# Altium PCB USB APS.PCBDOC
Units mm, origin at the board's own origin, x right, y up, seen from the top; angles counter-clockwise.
Board outline 92.58 x 101.6 mm, 2 copper layers (Top Layer, Bottom Layer); 29 components, 24 nets, 157 pads, 0 vias.
Unrouted connection lines stored in the file: 13.
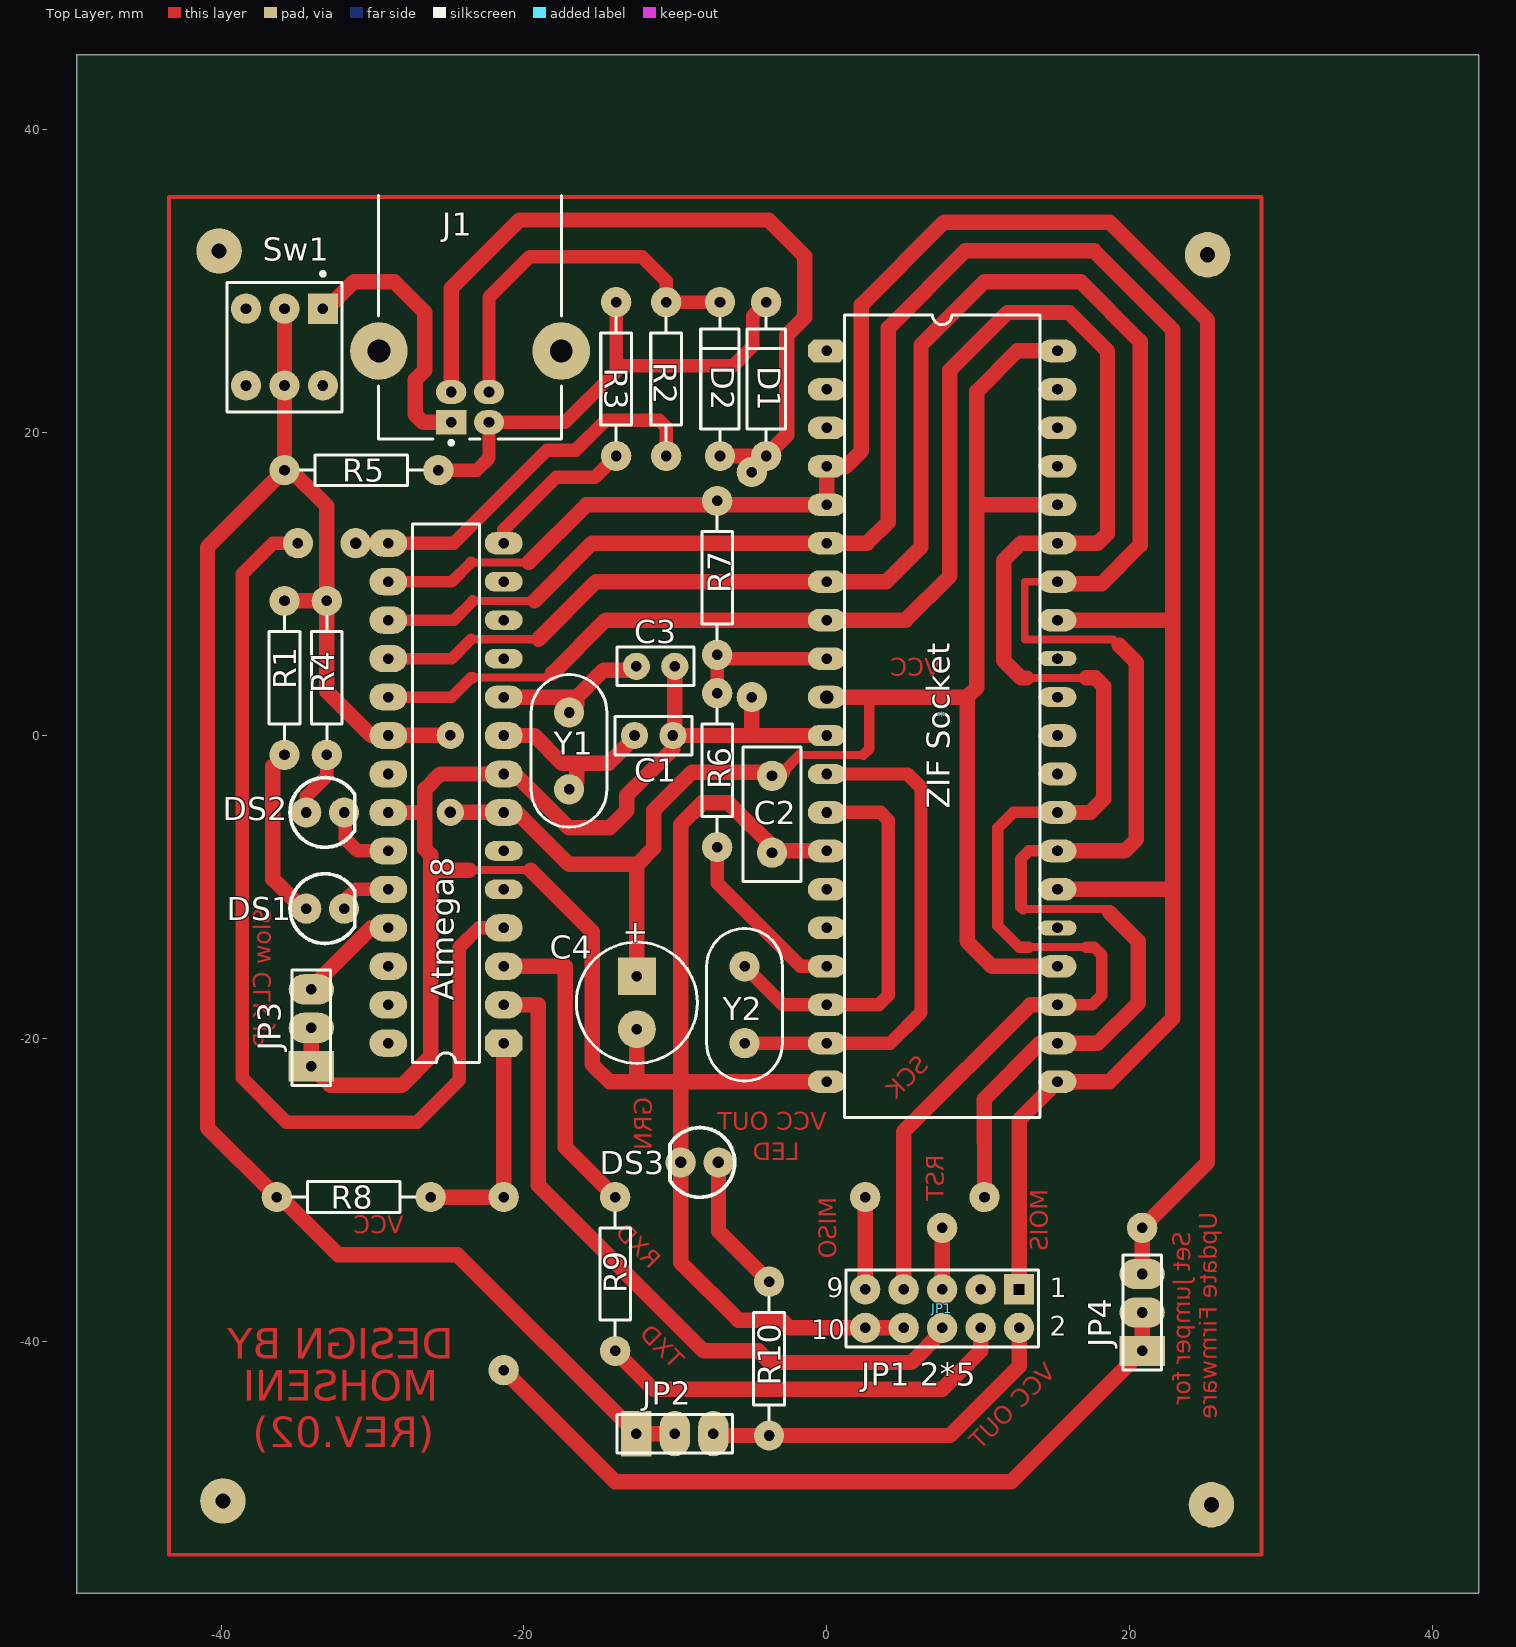
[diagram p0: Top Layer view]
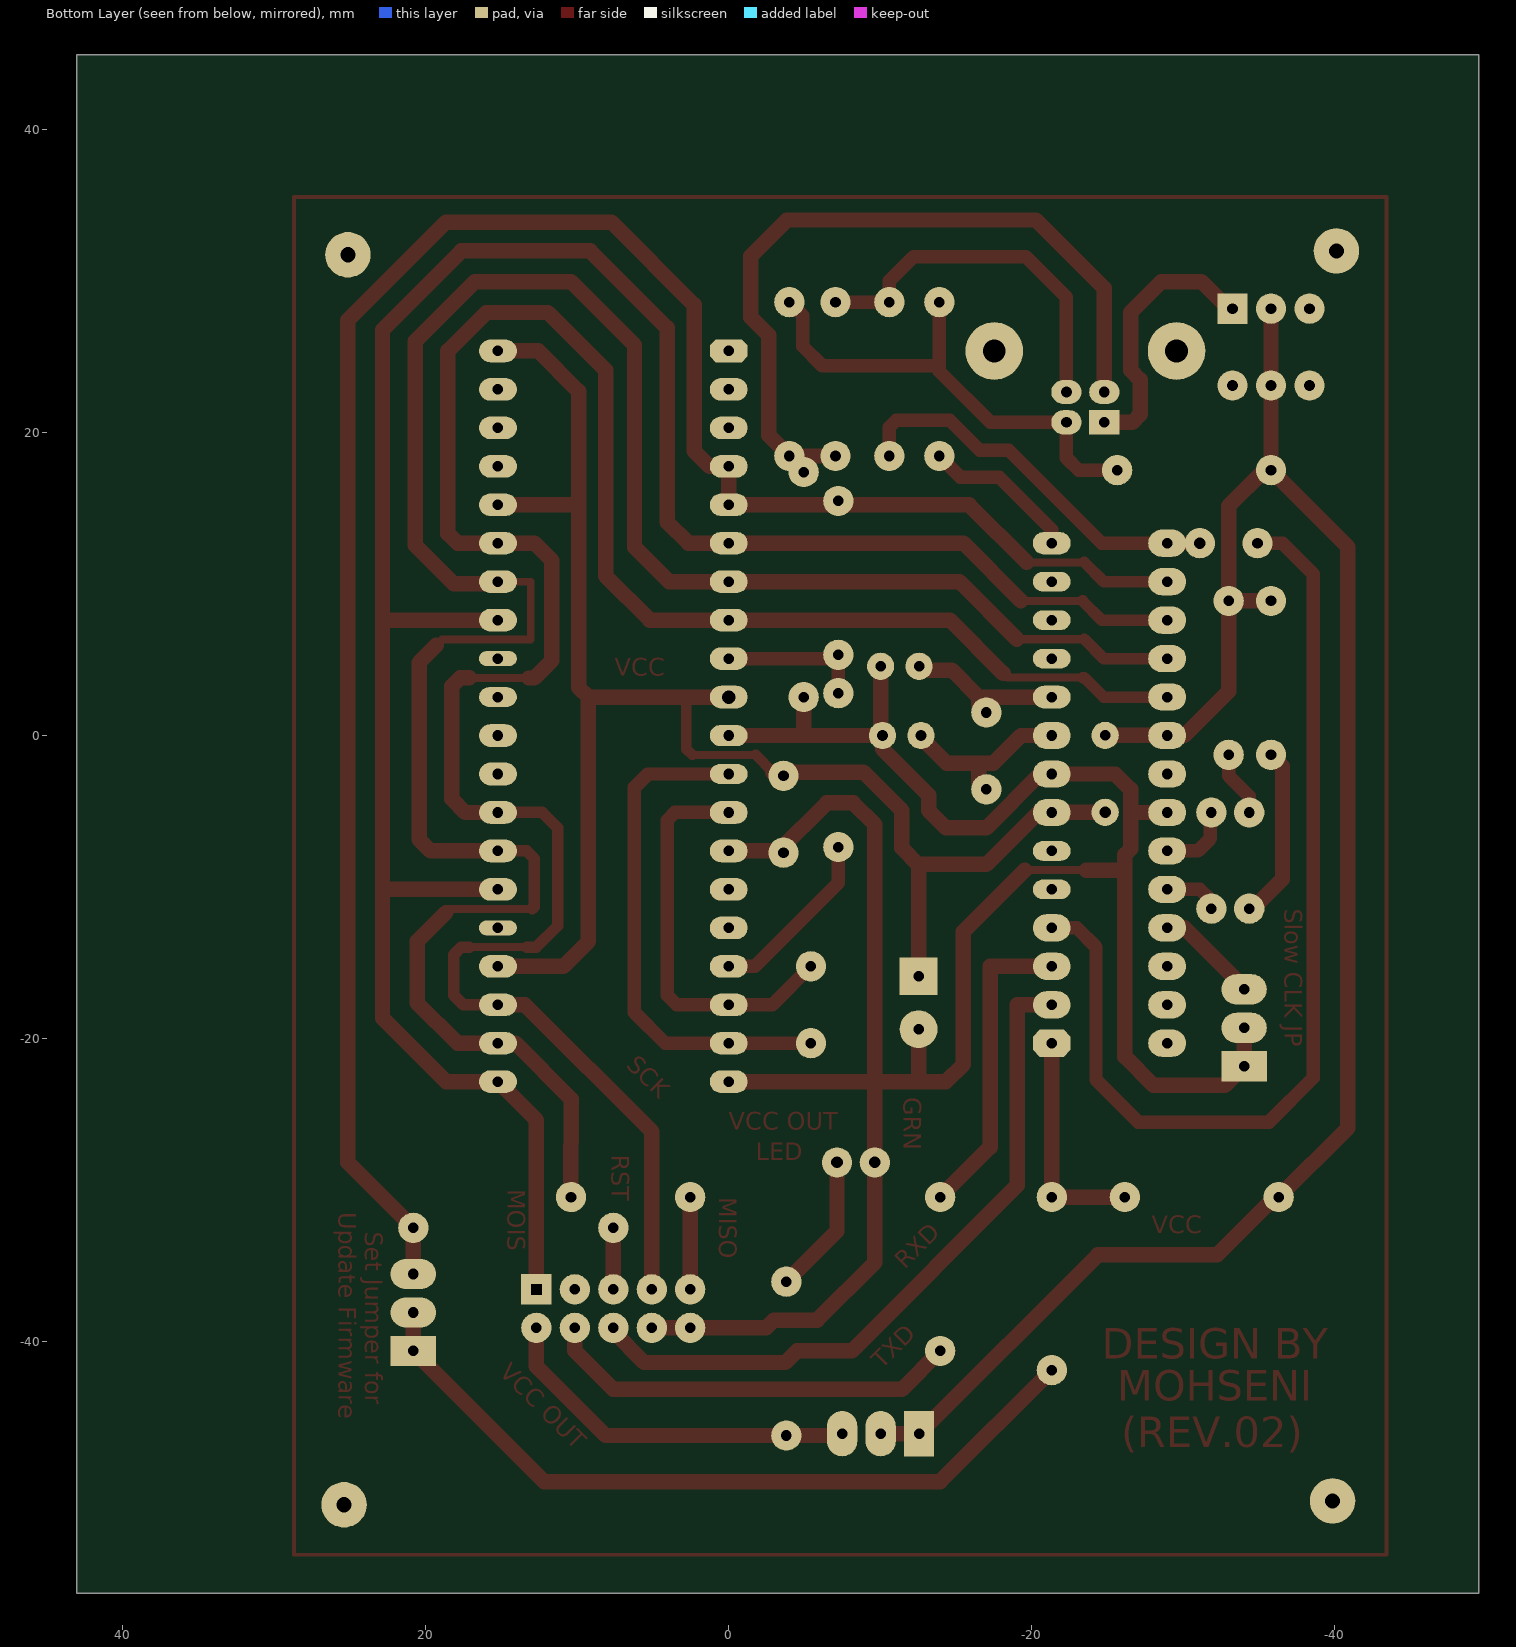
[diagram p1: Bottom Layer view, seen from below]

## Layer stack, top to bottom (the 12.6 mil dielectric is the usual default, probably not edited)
Top Solder: solder mask 0.0102, Solder Resist, Dk 3.5
Top Layer: signal copper 0.0356
Dielectric1: dielectric 0.32, FR-4, Dk 4.8
Bottom Layer: signal copper 0.0356
Bottom Solder: solder mask 0.0102, Solder Resist, Dk 3.5

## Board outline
-49.53,-56.642 43.053,-56.642 43.053,44.958 -49.53,44.958

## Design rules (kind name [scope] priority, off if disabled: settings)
Clearance [All] p1: gap=0.254
FabricationTestPointUsage TestPointUsage [All] p1: valid=0 allowmultiple=FALSE
FabricationTestpoint Testpoint [All] p1: side=3 testpointundercomponent=TRUE minsize=1.016 maxsize=2.54 preferedsize=1.524 minholesize=0 maxholesize=1.016 preferedholesize=0.813 testpointgrid=0.025 allowsidetop=TRUE allowsidebottom=TRUE usegrid=TRUE gridtolerance=0
PolygonConnect [All] p1: connectstyle=Relief reliefconductorwidth=0.254 reliefentries=4 polygonreliefangle="90 Angle" airgapwidth=0.254
RoutingVias [All] p1: holewidth=0.711 width=1.27 viastyle="Through Hole" minholewidth=0.711 minwidth=1.27 maxholewidth=0.711 maxwidth=1.27
SolderMaskExpansion [All] p1: expansion=0.102
UnpouredPolygon [All] p1: allowunpoured=FALSE
Width [All] p1: maxlimit=8 minlimit=0.254 preferedwidth=1.016 bottomlayer_prefwidth=0.254 minimp=50.000000 maximp=50.000000 favimp=50.000000
27 further rules are at their usual default settings.

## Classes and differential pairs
component class "USB APS": * Atmega8 C1 C2 C3 C4 D1 D2 DS1 DS2 J1 JP1 JP3 R1 R2 R3 R4 R5 R6 R7 Sw1 Y1 Y2

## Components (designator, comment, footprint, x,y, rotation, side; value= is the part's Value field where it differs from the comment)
* "zif sucket" 40P6 7.62,1.27 r270 top
Atmega8 "ATmega8-16PC" 28P3 -25.146,-3.81 r90 top (schematic designator U1)
C1 "Cap" RAD-0.1 -11.43,0 r0 top
C2 "Cap" RAD-0.2 -3.617,-5.198 r90 top
C3 "Cap" RAD-0.1 -11.303,4.572 r0 top
C4 "Cap Pol1" CAPPR3.5-8x5 -12.541,-17.644 r270 top
D1 "D Zener" DIODE-0.4 -4.004,23.543 r90 top
D2 "D Zener" DIODE-0.4 -7.052,23.543 r90 top
DS1 "LED0" LED3mm#1 -31.877,-11.43 r180 top
DS2 "LED0" LED3mm#1 -31.877,-5.08 r180 top
DS3 "LED0" LED3mm#2 -9.652,-28.194 r0 top (schematic designator DS1)
J1 "1-1470156-1" 1-1470156 -23.556,35.696 r90 top
JP1 "Header 5X2" HDR2X5 2.54,-39.116 r0 top
JP2 "Header 3" HDR1X3 -12.573,-46.101 r0 top (schematic designator JP3)
JP3 "Header 3" HDR1X3 -34.036,-21.844 r90 top
JP4 "Header 3" HDR1X3 20.828,-40.64 r90 top (schematic designator JP3)
R1 "Res1" AXIAL-0.4 -35.814,3.81 r270 top
R2 "Res1" AXIAL-0.4 -10.608,23.543 r270 top
R3 "Res1" AXIAL-0.4 -13.91,23.543 r270 top
R4 "Res1" AXIAL-0.4 -33.02,3.81 r270 top
R5 "Res1" AXIAL-0.4 -30.734,17.526 r180 top
R6 "Res1" AXIAL-0.4 -7.239,-2.286 r90 top
R7 "Res1" AXIAL-0.4 -7.239,10.414 r90 top
R8 "Res1" AXIAL-0.4 -31.242,-30.48 r180 top (schematic designator R1)
R9 "Res1" AXIAL-0.4 -13.97,-35.56 r270 top (schematic designator R1)
R10 "Res1" AXIAL-0.4 -3.81,-41.148 r270 top (schematic designator R1)
Sw1 "SW-DPDT" DPDT-6 -35.814,25.654 r270 top (schematic designator S1)
Y1 "XTAL" "xtal - duplicate" -17.018,1.524 r270 top
Y2 "XTAL" "xtal - duplicate" -5.429,-20.32 r90 top

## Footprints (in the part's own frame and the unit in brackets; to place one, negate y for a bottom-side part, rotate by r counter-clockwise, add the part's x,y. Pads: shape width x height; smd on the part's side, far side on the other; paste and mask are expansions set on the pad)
1-1470156 [mm] "Connector; USB1.1, Type B, Thru-Hole; 4 Position; Right Angle"
  rect 1.6x2 hole 0.7: 1(-15.01,1.25)
  oval 1.6x2 hole 0.7: 2(-15.01,-1.25) 3(-13.01,-1.25) 4(-13.01,1.25)
  round 3.8 hole 1.5: 5(-10.3,6.02) 6(-10.3,-6.02)
  silkscreen extent -16.48,-6.05 -0.02,6.05
28P3 [mm] "DIP; 28 Leads; Row Spacing 7.62 mm; Pitch 2.54 mm"
  oct 1.8x2.5 hole 0.7: 1(-16.51,-3.81)
  oval 1.8x2.5 hole 0.7: 2(-13.97,-3.81) 3(-11.43,-3.81) 4(-8.89,-3.81) 7(-1.27,-3.81) 8(1.27,-3.81) 9(3.81,-3.81) 15(16.51,3.81) 16(13.97,3.81) 17(11.43,3.81) 18(8.89,3.81) 19(6.35,3.81) 20(3.81,3.81) 21(1.27,3.81) 22(-1.27,3.81) 23(-3.81,3.81) 24(-6.35,3.81) 25(-8.89,3.81) 26(-11.43,3.81) 27(-13.97,3.81) 28(-16.51,3.81)
  oval 1.3x2.5 hole 0.7: 5(-6.35,-3.81) 6(-3.81,-3.81) 11(8.89,-3.81) 12(11.43,-3.81) 13(13.97,-3.81)
  oval 1.5x2.5 hole 0.7: 10(6.35,-3.81) 14(16.51,-3.81)
  silkscreen extent -17.78,-2.23 17.78,2.23
40P6 [mm] "DIP; 40 Leads; Row Spacing 15.24 mm; Pitch 2.54 mm"
  oct 1.5x2.5 hole 0.7: 1(-24.13,-7.62)
  oval 1.5x2.5 hole 0.7: 2(-21.59,-7.62) 3(-19.05,-7.62) 4(-16.51,-7.62) 5(-13.97,-7.62) 6(-11.43,-7.62) 7(-8.89,-7.62) 8(-6.35,-7.62) 9(-3.81,-7.62) 13(6.35,-7.62) 14(8.89,-7.62) 15(11.43,-7.62) 16(13.97,-7.62) 17(16.51,-7.62) 18(19.05,-7.62) 19(21.59,-7.62) 20(24.13,-7.62) 21(24.13,7.62) 22(21.59,7.62) 23(19.05,7.62) 24(16.51,7.62) 26(11.43,7.62) 27(8.89,7.62) 28(6.35,7.62) 29(3.81,7.62) 30(1.27,7.62) 33(-6.35,7.62) 34(-8.89,7.62) 35(-11.43,7.62) 36(-13.97,7.62) 37(-16.51,7.62) 38(-19.05,7.62) 39(-21.59,7.62) 40(-24.13,7.62)
  oval 1.5x2.5 hole 0.9: 10(-1.27,-7.62)
  oval 1.4x2.5 hole 0.7: 11(1.27,-7.62)
  oval 1.3x2.5 hole 0.7: 12(3.81,-7.62) 31(-1.27,7.62)
  oval 1x2.5 hole 0.7: 25(13.97,7.62) 32(-3.81,7.62)
  silkscreen extent -26.5,-6.45 26.5,6.45
AXIAL-0.4 [mm] "Resistor; 2 Leads"
  round 2 hole 0.7: 1(-5.08,0) 2(5.08,0)
  silkscreen extent -4.06,-1.02 4.06,1.02
CAPPR3.5-8x5 [mm]
  rect 2.5x2.5 hole 0.7: 1(-1.75,0)
  round 2.5 hole 0.7: 2(1.75,0)
  silkscreen extent -4,-4 4,4
DIODE-0.4 [mm]
  round 2 hole 0.7: 1(-5.08,0) 2(5.08,0)
  silkscreen extent -4.06,-1.27 4.06,1.27
DPDT-6 [mm] "Double-Pole, Double-Throw Switch; 6 Leads"
  rect 2x2 hole 0.7: 1(-2.54,2.54)
  round 2 hole 0.7: 2(-2.54,0) 3(-2.54,-2.54) 4(2.54,-2.54) 5(2.54,0) 6(2.54,2.54)
  silkscreen extent -4.96,-3.81 4.28,3.81
HDR1X3 [mm] "Connector; Header; 3 Position"
  rect 2x3 hole 0.7: 1(0,0)
  oval 2x3 hole 0.7: 2(2.54,0) 3(5.08,0)
  silkscreen extent -1.27,-1.27 6.35,1.27
HDR2X5 [mm] "Connector; Header; 5x2 Position"
  round 2 hole 0.7: 1(0,0) 2(0,2.54) 3(2.54,0) 4(2.54,2.54) 5(5.08,0) 6(5.08,2.54) 7(7.62,0) 8(7.62,2.54) 9(10.16,0)
  rect 2x2 hole 0.7 square: 10(10.16,2.54)
  silkscreen extent -1.27,-1.27 11.43,3.81
LED3mm#1 [mm]
  round 2 hole 0.7: 1(2.5,0) 2(0,0)
  silkscreen extent -0.7,-2.3 3.57,2.3
LED3mm#2 [mm]
  round 2 hole 0.762: 1(2.5,0) 2(0,0)
  silkscreen extent -0.7,-2.3 3.57,2.3
RAD-0.1 [mm]
  round 1.8 hole 0.7: 1(-1.27,0) 2(1.27,0)
  silkscreen extent -2.54,-1.27 2.54,1.27
RAD-0.2 [mm]
  round 2 hole 0.7: 1(-2.54,0) 2(2.54,0)
  silkscreen extent -4.44,-1.91 4.44,1.91
"xtal - duplicate" [mm]
  round 2 hole 0.7: 1(0,0) 2(5.08,0)
  silkscreen extent -2.5,-2.5 7.58,2.5

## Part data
*: library part Component_1
Atmega8: "8-Bit AVR Microcontroller with 8K Bytes of In-System Programmable Flash Memory"
C1 C2 C3: "Capacitor"
C4: "Polarized Capacitor (Radial)"
D1 D2: "Zener Diode"
DS1 DS2 DS3: "Typical INFRARED GaAs LED"
J1: "USB 1.1, Right Angle, Thru-Hole, B Type, Receptacle, 4 Position, White"
JP1: "Header, 5-Pin, Dual row"
JP2 JP3 JP4: "Header, 3-Pin"
R1 R2 R3 R4 R5 R6 R7 R8 R9 R10: "Resistor"
Sw1: "Double-Pole, Double-Throw Switch"
Y1 Y2: "Crystal Oscillator"

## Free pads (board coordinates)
  round 3 hole 1: 0(-40.132,32.004) 0(-39.878,-50.546) 0(25.146,31.75) 0(25.4,-50.8)
  round 2 hole 0.7: 0(-34.925,12.7) 2(-21.336,-30.48) 3(-21.336,-41.91) 4(10.414,-30.48) 5(2.54,-30.48) 7(-4.953,17.399) 8(-4.953,2.54)
  round 1.8 hole 0.762: 0(-24.86,-5.071)
  round 1.8 hole 0.7: 1(-24.86,0.009)
  round 2 hole 0.762: 2(-31.115,12.7)
  round 2 hole 0.7 paste+1 mask+0.102: 3(7.62,-32.512) 3(20.828,-32.512)

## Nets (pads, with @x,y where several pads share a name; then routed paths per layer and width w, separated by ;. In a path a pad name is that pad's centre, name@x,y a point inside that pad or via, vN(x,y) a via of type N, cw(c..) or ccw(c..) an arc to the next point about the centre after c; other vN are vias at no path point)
CLK: JP1.8
GND: *.11 *.14 *.20 Atmega8.8 Atmega8.22 C1.2 C2.1 C3.2 C4.2 D1.1 D2.1 DS3.2 J1.4 JP1.1 JP1.3 JP3.1 JP3.2 pad.7 pad.8 | length 218.6
  Top Layer w0.53: -23.622,-8.89 -19.558,-8.89
  Top Layer w1.016: JP3.2 JP3.1 -32.775,-23.105 -28.058,-23.105 -26.162,-21.209 -26.162,-8.89 ; Atmega8.22 -26.67,-5.08 -26.543,-5.207 ; J1.4 -24.806,29.527 -20.288,34.045 -3.838,34.045 -1.464,31.671 -1.464,27.607 -2.648,26.423 -2.648,19.819 D1.1 D2.1 ; -23.622,-8.89 -26.162,-8.89 ; Atmega8.8@-21.59,-2.794 -21.844,-2.54 -25.527,-2.54 -26.543,-3.556 -26.543,-5.207 ; Atmega8.8 -20.574,-2.54 -17.018,-6.096 -14.351,-6.096 -13.208,-4.953 -13.208,-3.937 -10.16,-0.889 -10.16,-0.127 C1.2@-10.033,0 ; -19.558,-8.89 -15.494,-12.954 -15.494,-21.717 -14.351,-22.86 -9.652,-22.86 ; -12.541,-22.828 C4.2 ; C3.2@-10.033,4.318 C1.2@-10.033,0 ; pad.8 -4.953,0 ; *.20 -9.652,-22.86 ; *.14 -3.302,-7.62 -6.477,-4.445 -8.223,-4.445 -9.652,-5.874 -9.652,-22.86 ; *.11 -4.953,0 ; JP1.3 JP1.1 -2.476,-39.116 -2.984,-38.608 -5.842,-38.608 -9.652,-34.798 -9.652,-22.86 ; -26.543,-5.207 -26.543,-7.493 -26.162,-7.874 -26.162,-8.89 ; C1.2@-10.033,0 -4.953,0
MISO: *.7 *.22 *.27 *.34 Atmega8.18 JP1.2 pad.4 pad.5 | length 164.9
  Top Layer w0.254: *.27 *.27@16.129,-7.62 ; *.34 *.34@15.367,10.16
  Top Layer w0.381: 18.427,-11.442 18.669,-11.684
  Top Layer w0.508: 13.093,6.338 13.081,6.35 13.081,10.16 *.34 ; 18.935,6.338 19.304,5.969
  Top Layer w0.53: -23.495,6.359 -19.041,6.359 ; 12.966,-11.442 18.427,-11.442 ; 13.093,6.338 18.935,6.338
  Top Layer w0.762: Atmega8.18 -24.774,5.08 -23.495,6.359 ; 12.966,-11.442 12.827,-11.303 12.827,-8.128 13.335,-7.62 *.27
  Top Layer w1.016: -19.041,6.359 -15.24,10.16 *.7 3.937,10.16 6.223,12.446 6.223,25.781 10.414,29.972 16.764,29.972 20.701,26.035 20.701,12.573 18.161,10.033 *.34@15.367,10.033 ; JP1.2 pad.5 ; pad.4@10.42,-29.972 10.401,-24.003 14.084,-20.32 *.22 17.907,-20.32 20.574,-17.653 20.574,-13.589 18.669,-11.684 ; *.27 19.685,-7.62 20.447,-6.858 20.447,4.826 19.304,5.969
MOIS: *.6 *.21 *.26 *.33 Atmega8.17 JP1.10 | length 159.7
  Top Layer w0.254: *.26 18.415,-10.16
  Top Layer w0.508: Atmega8.17@-29.083,7.62 Atmega8.17
  Top Layer w0.53: -23.368,8.89 -19.304,8.89
  Top Layer w0.762: Atmega8.17 -24.638,7.62 -23.368,8.89
  Top Layer w1.016: -19.304,8.89 -15.494,12.7 *.6 2.667,12.7 4.064,14.097 4.064,26.924 9.144,32.004 17.653,32.004 22.86,26.797 22.86,7.62 ; JP1.10 12.7,-25.4 *.21 18.669,-22.86 22.86,-18.669 22.86,-10.16 ; *.26 22.86,-10.16 ; *.33 22.86,7.62 ; 22.86,-10.16 22.86,7.62
NetD1_2: D1.2 J1.2 R3.1 R5.1 | length 32.7
  Top Layer w0.889: R5.1@-25.146,17.526 -23.114,17.526 -22.306,18.334 J1.2 -17.287,20.686 -13.91,24.063 -13.91,24.432 ; R3.1 -13.91,24.432 ; D1.2 -4.893,27.734 -4.893,25.702 -6.163,24.432 -13.91,24.432
NetD2_2: D2.2 J1.3 R2.1 | length 24.7
  Top Layer w0.889: J1.3 -22.306,28.951 -19.625,31.632 -12.22,31.632 -10.608,30.02 R2.1 D2.2
NetDS1_1: DS1.1 R1.2 | length 11.5
  Top Layer w1.016: R1.2 -36.576,-2.032 -36.576,-9.485 DS1.1@-34.504,-11.557
NetDS1_2: Atmega8.24 DS1.2 | length 3.7
  Top Layer w0.889: DS1.2@-31.75,-11.43 -31.75,-10.795 -31.115,-10.16 Atmega8.24
NetDS2_1: DS2.1 R4.2 | length 4.9
  Top Layer w0.889: DS2.1@-34.377,-5.588 -34.377,-4.024 -33.02,-2.667 R4.2
NetDS2_2: Atmega8.23 DS2.2 | length 5
  Top Layer w0.889: DS2.2@-31.813,-5.016 -31.813,-6.794 -30.988,-7.62 Atmega8.23
NetJ1_1: J1.1 Sw1.1 Sw1.4 | length 17.4
  Top Layer w1.016: Sw1.1@-32.861,28.33 -31.219,29.972 -28.575,29.972 -26.543,27.94 -26.543,24.13 -27.178,23.495 -27.178,21.209 -26.655,20.686 J1.1
NetJP3_3: Atmega8.25 JP3.3 | length 6.8
  Top Layer w1.016: JP3.3@-34.099,-16.7 -30.099,-12.7 Atmega8.25
NetR2_2: Atmega8.4 Atmega8.15 pad.0@-34.925,12.7 pad.2@-31.115,12.7 R2.2 | length 93.1
  Top Layer w0.889: pad.0@-34.544,12.7 -36.576,12.7 -38.608,10.668 -38.608,-22.606 -35.687,-25.527 -27.051,-25.527 -24.257,-22.733 -24.257,-13.97 -22.987,-12.7 Atmega8.4 ; pad.2@-31.115,12.7 Atmega8.15 -24.638,12.7 -18.494,18.844 -16.589,18.844 -14.605,20.828 -11.068,20.828 -10.608,20.368 R2.2
NetR3_2: Atmega8.14 R3.2 | length 10.3
  Top Layer w0.889: Atmega8.14 -21.336,13.589 -17.859,17.066 -15.307,17.066 R3.2
Reset: 
RST: *.4 *.5 *.9 *.17 Atmega8.1 Atmega8.16 JP1.6 JP4.1 JP4.2 JP4.3 pad.2@-21.336,-30.48 pad.3 R6.1 R6.2 R7.1 R7.2 R8.1 | length 230.2
  Top Layer w0.53: -23.495,11.43 -19.685,11.43
  Top Layer w0.762: Atmega8.16 -24.765,10.16 -23.495,11.43
  Top Layer w0.889: R6.1@-7.493,-7.62 R6.1 -7.239,-9.738 -1.737,-15.24 *.17 ; R6.2 -7.239,5.08 *.9
  Top Layer w1.016: R8.1 pad.2@-21.336,-30.48 ; pad.3@-21.336,-41.91 -13.97,-49.276 12.192,-49.276 JP4.1 JP4.2 ; pad.2@-21.336,-29.972 Atmega8.1 ; -19.685,11.43 -15.875,15.24 *.5 *.4 1.27,17.78 2.286,18.796 2.286,28.448 7.747,33.909 18.669,33.909 25.146,27.432 25.146,-28.194 20.828,-32.512 JP4.3 ; JP1.6 pad.3@7.62,-32.512
RXD: Atmega8.2 JP1.5 | length 46.8
  Top Layer w1.016: Atmega8.2 -19.05,-17.78 -19.05,-29.718 -8.128,-40.64 -4.508,-40.64 -3.746,-41.402 5.588,-41.402 7.62,-39.37 JP1.5
SCK: *.8 *.23 *.28 *.35 Atmega8.19 JP1.4 | length 159.9
  Top Layer w0.508: -18.406,3.819 -18.12,4.105
  Top Layer w0.53: -23.368,3.819 -18.406,3.819 ; 13.208,3.798 17.145,3.81 ; 13.335,-13.97 17.145,-13.97
  Top Layer w0.762: Atmega8.19 -24.774,2.54 -23.495,3.819 -23.368,3.819 ; 13.335,-13.97 12.7,-13.97 11.303,-12.573 11.303,-6.096 12.319,-5.08 *.28 ; *.23 17.526,-17.78 18.161,-17.145 18.161,-14.478 17.653,-13.97 17.145,-13.97
  Top Layer w1.016: -18.12,4.105 -14.605,7.62 *.8 5.207,7.62 8.128,10.541 8.128,24.13 11.938,27.94 16.002,27.94 18.542,25.4 18.542,13.335 17.907,12.7 *.35 12.827,12.7 11.684,11.557 11.684,4.953 12.839,3.798 13.208,3.798 ; JP1.4@5.074,-36.576 5.074,-26.156 13.449,-17.78 *.23 ; *.28 17.399,-5.08 18.288,-4.191 18.288,3.267 17.745,3.81 17.145,3.81
TXD: Atmega8.3 JP1.7 R9.1 R9.2 | length 48.4
  Top Layer w1.016: Atmega8.3 -17.272,-15.24 -17.272,-27.178 R9.1 ; R9.2 -11.43,-43.18 7.62,-43.18 10.16,-40.64 JP1.7
VCC: *.10 *.24 *.36 *.40 Atmega8.7 Atmega8.20 C2.2 C4.1 DS3.1 JP1.9 JP2.1 JP2.2 JP2.3 pad.0@-24.86,-5.071 pad.1 R1.1 R4.1 R5.2 R8.2 R10.1 R10.2 Sw1.2 Sw1.5 | length 265.1
  Top Layer w0.53: -1.778,-1.27 2.413,-1.27
  Top Layer w0.7: C2.2@-2.921,-2.413 -1.778,-1.27 ; 2.413,-1.27 2.794,-0.889 2.794,2.54
  Top Layer w1.016: R1.1 R4.1 ; R5.2@-35.814,18.034 Sw1.5 Sw1.2 ; R4.1@-32.893,8.89 R4.1 ; pad.0@-24.86,-5.071 -21.345,-5.071 Atmega8.7 -20.447,-5.08 -17.018,-8.509 -12.509,-8.509 ; pad.1 -28.947,0.009 Atmega8.20 -30.099,0 -33.02,2.921 R4.1 ; C4.1 -12.541,-8.541 -12.509,-8.509 ; JP2.2 JP2.1 -24.384,-34.29 -32.258,-34.29 -36.068,-30.48 R8.2 -40.894,-25.908 -40.894,12.446 R5.2 -35.401,17.526 -33.02,15.145 R4.1 ; JP2.3@-7.493,-46.228 R10.2@-3.302,-46.228 ; DS3.1@-7.152,-28.702 -7.152,-32.726 R10.1 ; R10.2@-3.048,-46.228 8.128,-46.228 12.7,-41.656 JP1.9 ; C2.2@-2.921,-2.413 -8.89,-2.413 -11.43,-4.953 -11.43,-7.43 -12.509,-8.509 ; *.10 2.794,2.54 9.271,2.54 ; *.24 10.922,-15.24 9.271,-13.589 9.271,2.54 ; *.36 9.906,15.24 ; *.40 12.573,25.4 9.906,22.733 9.906,15.24 ; 9.271,2.54 9.906,3.175 9.906,15.24
X1: Atmega8.9 C1.1 Y1.2 | length 12.2
  Top Layer w1.016: Atmega8.9 -19.304,0 -17.47,-1.834 -16.51,-1.834 ; Y1.2 -16.51,-3.048 -16.51,-1.834 ; C1.1@-12.573,0 -14.407,-1.834 -16.51,-1.834
X2: Atmega8.10 C3.1 Y1.1 | length 10.1
  Top Layer w1.016: Atmega8.10 -16.51,2.54 ; Y1.1 -16.51,2.032 -16.51,2.54 ; C3.1@-13.208,4.318 -14.732,4.318 -16.51,2.54
X21: *.12 *.19 Y2.1 | length 33.9
  Top Layer w0.889: Y2.1 *.19 4.191,-20.32 6.223,-18.288 6.223,-3.429 5.334,-2.54 *.12
X22: *.13 *.18 Y2.2 | length 26.6
  Top Layer w0.889: Y2.2 -2.889,-17.78 *.18 3.429,-17.78 4.064,-17.145 4.064,-5.588 3.556,-5.08 *.13
pads on no net: *.1 *.2 *.3 *.15 *.16 *.25 *.29 *.30 *.31 *.32 *.37 *.38 *.39 Atmega8.5 Atmega8.6 Atmega8.11 Atmega8.12 Atmega8.13 Atmega8.21 Atmega8.26 Atmega8.27 Atmega8.28 J1.5 J1.6 Sw1.3 Sw1.6
copper on no net: | length 323.6
  Top Layer w0.254: -43.434,-54.102 -43.434,35.56 28.702,35.56 28.702,-54.102 -43.434,-54.102

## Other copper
Top Layer:
  text "VCC" at 7.52,3.556 h2
  text "Slow CLK JP" at -36.322,-11.43 h2 r90
  text "SCK" at 7.112,-22.098 h2 r45
  text "GRN" at -11.176,-23.876 h2 r90
  text "VCC OUT" at 0,-26.416 h2
  text "RST" at 8.128,-27.686 h2 r90
  text "LED" at -1.778,-28.448 h2
  text "MOIS" at 14.986,-29.972 h2 r90
  text "MISO" at 1.016,-30.48 h2 r90
  text "Update Firmware" at 26.162,-31.496 h2 r90
  text "Set Jumper for" at 24.384,-32.766 h2 r90
  text "VCC" at -27.94,-33.274 h2
  text "RXD" at -11.938,-35.56 h2 r315
  text "DESIGN BY" at -24.638,-41.148 h2
  text "TXD" at -10.414,-42.164 h2 r315
  text "VCC OUT" at 15.494,-42.418 h2 r45
  text "MOHSENI" at -25.654,-43.942 h2
  text "(REV.02)" at -25.908,-46.99 h2

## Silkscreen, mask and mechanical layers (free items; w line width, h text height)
Top Overlay:
  text "ZIF Socket" at 8.128,-4.826 h1.52 r90
  text "JP1 2*5" at 2.286,-42.926 h1.52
